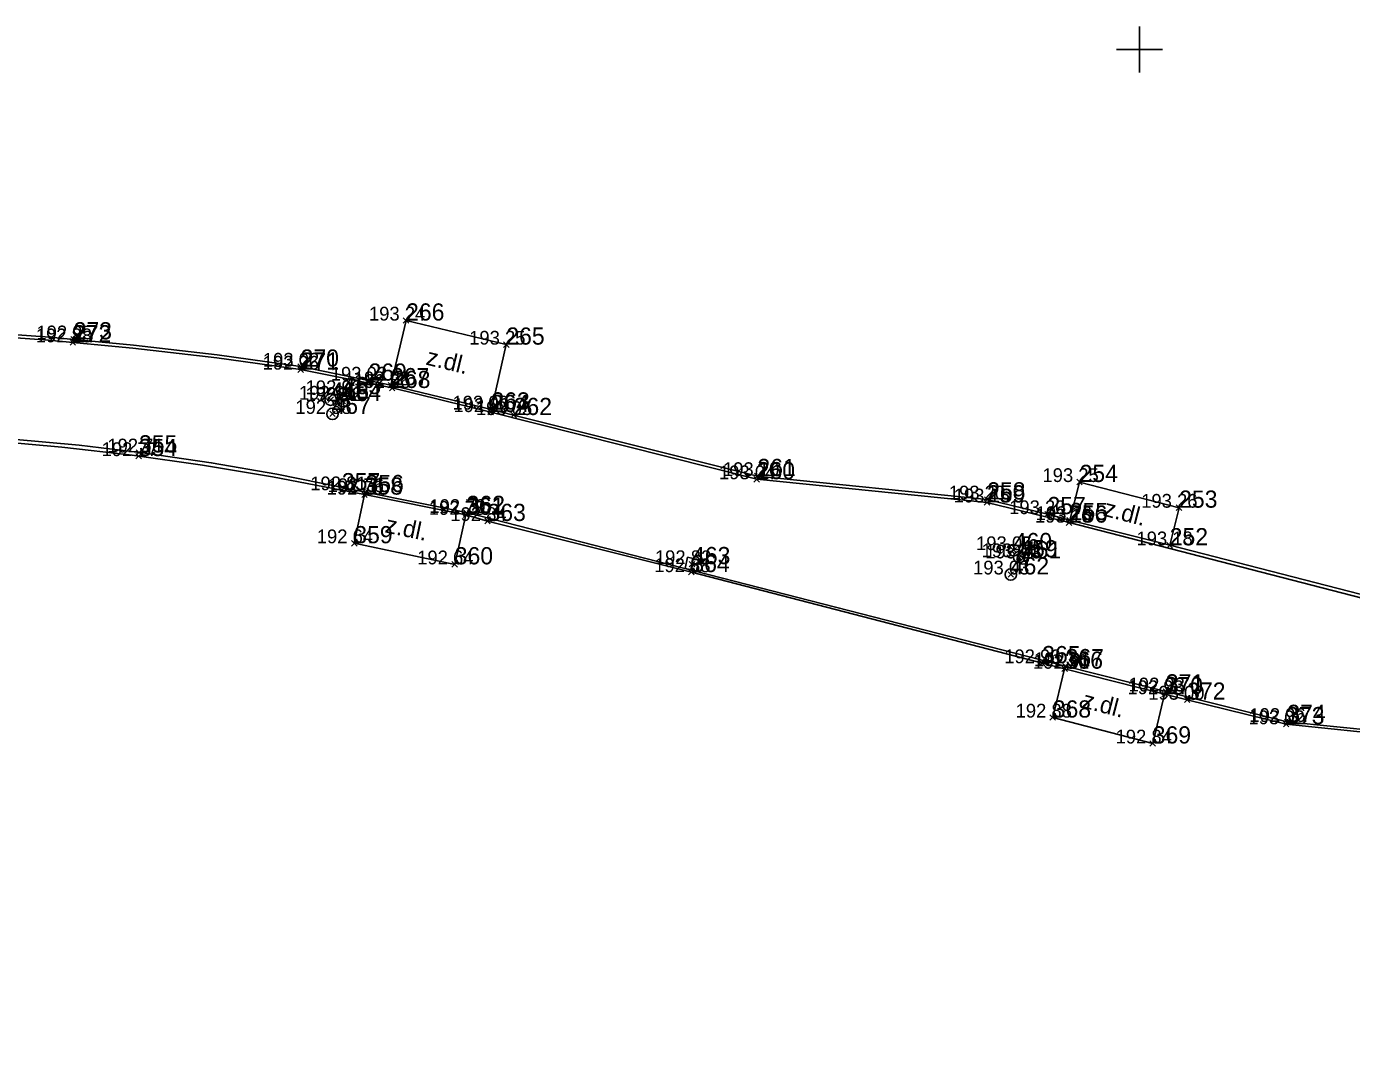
# Model space of a CAD drawing. Extents: x -706861 to -706379, y -1036456 to -1036201.
# Drawn here: x -706748.5 to -706690.8, y -1036344 to -1036299 of the extents above; entities that cross this region are included whole.
import ezdxf

# ---------------------------------------------------------------- set-up
doc = ezdxf.new("R2010")
doc.units = 0
for name, color, linetype in [('18_popisy', 7, 'Continuous'), ('29_vodovod', 7, 'Continuous'), ('30_kanalizace splašková', 7, 'Continuous'), ('40_plochy', 7, 'Continuous'), ('51_body polohopisu_značky', 7, 'Continuous'), ('52_body polohopisu_čísla', 7, 'Continuous'), ('53_body polohopisu_výšky', 7, 'Continuous'), ('54_body polohopisu_čísla nadbytečné pro kreslení', 7, 'Continuous'), ('5_rozhraní ploch', 7, 'Continuous'), ('60_mapový rám_legenda', 7, 'Continuous')]:
    doc.layers.add(name, color=color, linetype=linetype)

msp = doc.modelspace()

# ---------------------------------------------------------------- linework, layer by layer
at = {"layer": '29_vodovod'}
for centre in [(-706734.74, -1036315.03), (-706734.74, -1036315.33), (-706705.48, -1036321.83), (-706705.24, -1036322.14)]:
    msp.add_circle(centre, 0.25, dxfattribs=at)
at = {"layer": '30_kanalizace splašková'}
msp.add_line((-706719.456, -1036322.196), (-706719.564, -1036322.684), dxfattribs=at)
msp.add_lwpolyline([(-706719.701, -1036322.142), (-706719.809, -1036322.63), (-706719.32, -1036322.739), (-706719.211, -1036322.25)], close=True, dxfattribs=at)
for centre in [(-706735.27, -1036315.27), (-706735.19, -1036315.89), (-706705.08, -1036322.19), (-706705.61, -1036322.89)]:
    msp.add_circle(centre, 0.25, dxfattribs=at)
at = {"layer": '40_plochy'}
for points in [[(-706732.64, -1036314.64), (-706731.98, -1036311.82), (-706727.61, -1036312.87), (-706728.26, -1036315.7)], [(-706703.04, -1036320.52), (-706702.61, -1036318.86), (-706698.27, -1036319.98), (-706698.68, -1036321.62)], [(-706733.79, -1036319.41), (-706734.24, -1036321.53), (-706729.86, -1036322.45), (-706729.37, -1036320.29)], [(-706703.26, -1036327), (-706703.78, -1036329.13), (-706699.42, -1036330.26), (-706698.9, -1036328.11)]]:
    msp.add_lwpolyline(points, close=True, dxfattribs=at)
for points in [[(-706751.26, -1036312.41), (-706747.58, -1036312.68), (-706743.9, -1036313.03), (-706740.24, -1036313.45), (-706736.58, -1036313.96), (-706732.59, -1036314.76), (-706728.29, -1036315.81), (-706716.69, -1036318.74), (-706706.65, -1036319.75), (-706703.07, -1036320.63), (-706684.54, -1036325.41)], [(-706683.45, -1036330.34), (-706693.55, -1036329.31), (-706698.85, -1036327.99), (-706703.22, -1036326.89), (-706729.35, -1036320.19), (-706733.75, -1036319.3), (-706737.61, -1036318.52), (-706740.48, -1036318.02), (-706743.36, -1036317.6), (-706746.24, -1036317.25), (-706749.14, -1036316.99)]]:
    msp.add_lwpolyline(points, dxfattribs=at)
at = {"layer": '51_body polohopisu_značky'}
for points in [[(-706732.1, -1036311.94), (-706731.86, -1036311.7)], [(-706732.1, -1036311.7), (-706731.86, -1036311.94)], [(-706746.63, -1036312.89), (-706746.39, -1036312.65)], [(-706746.63, -1036312.65), (-706746.39, -1036312.89)], [(-706746.6, -1036312.76), (-706746.36, -1036312.52)], [(-706746.6, -1036312.52), (-706746.36, -1036312.76)], [(-706727.73, -1036312.99), (-706727.49, -1036312.75)], [(-706727.73, -1036312.75), (-706727.49, -1036312.99)], [(-706736.7, -1036313.95), (-706736.46, -1036313.71)], [(-706736.7, -1036313.71), (-706736.46, -1036313.95)], [(-706736.7, -1036314.08), (-706736.46, -1036313.84)], [(-706736.7, -1036313.84), (-706736.46, -1036314.08)], [(-706733.74, -1036314.56), (-706733.5, -1036314.32)], [(-706733.74, -1036314.32), (-706733.5, -1036314.56)], [(-706732.76, -1036314.76), (-706732.52, -1036314.52)], [(-706732.76, -1036314.52), (-706732.52, -1036314.76)], [(-706732.71, -1036314.88), (-706732.47, -1036314.64)], [(-706732.71, -1036314.64), (-706732.47, -1036314.88)], [(-706735.39, -1036315.39), (-706735.15, -1036315.15)], [(-706735.39, -1036315.15), (-706735.15, -1036315.39)], [(-706734.86, -1036315.15), (-706734.62, -1036314.91)], [(-706734.86, -1036314.91), (-706734.62, -1036315.15)], [(-706734.86, -1036315.45), (-706734.62, -1036315.21)], [(-706734.86, -1036315.21), (-706734.62, -1036315.45)], [(-706735.31, -1036316.01), (-706735.07, -1036315.77)], [(-706735.31, -1036315.77), (-706735.07, -1036316.01)], [(-706728.41, -1036315.93), (-706728.17, -1036315.69)], [(-706728.41, -1036315.69), (-706728.17, -1036315.93)], [(-706728.38, -1036315.82), (-706728.14, -1036315.58)], [(-706728.38, -1036315.58), (-706728.14, -1036315.82)], [(-706727.41, -1036316.06), (-706727.17, -1036315.82)], [(-706727.41, -1036315.82), (-706727.17, -1036316.06)], [(-706743.75, -1036317.69), (-706743.51, -1036317.45)], [(-706743.75, -1036317.45), (-706743.51, -1036317.69)], [(-706743.76, -1036317.85), (-706743.52, -1036317.61)], [(-706743.76, -1036317.61), (-706743.52, -1036317.85)], [(-706716.81, -1036318.86), (-706716.57, -1036318.62)], [(-706716.81, -1036318.62), (-706716.57, -1036318.86)], [(-706716.78, -1036318.72), (-706716.54, -1036318.48)], [(-706716.78, -1036318.48), (-706716.54, -1036318.72)], [(-706702.73, -1036318.98), (-706702.49, -1036318.74)], [(-706702.73, -1036318.74), (-706702.49, -1036318.98)], [(-706734.9, -1036319.34), (-706734.66, -1036319.1)], [(-706734.9, -1036319.1), (-706734.66, -1036319.34)], [(-706733.91, -1036319.53), (-706733.67, -1036319.29)], [(-706733.91, -1036319.29), (-706733.67, -1036319.53)], [(-706733.87, -1036319.42), (-706733.63, -1036319.18)], [(-706733.87, -1036319.18), (-706733.63, -1036319.42)], [(-706706.77, -1036319.87), (-706706.53, -1036319.63)], [(-706706.77, -1036319.63), (-706706.53, -1036319.87)], [(-706706.76, -1036319.74), (-706706.52, -1036319.5)], [(-706706.76, -1036319.5), (-706706.52, -1036319.74)], [(-706698.39, -1036320.1), (-706698.15, -1036319.86)], [(-706698.39, -1036319.86), (-706698.15, -1036320.1)], [(-706729.49, -1036320.41), (-706729.25, -1036320.17)], [(-706729.49, -1036320.17), (-706729.25, -1036320.41)], [(-706729.46, -1036320.33), (-706729.22, -1036320.09)], [(-706729.46, -1036320.09), (-706729.22, -1036320.33)], [(-706728.55, -1036320.68), (-706728.31, -1036320.44)], [(-706728.55, -1036320.44), (-706728.31, -1036320.68)], [(-706704.13, -1036320.38), (-706703.89, -1036320.14)], [(-706704.13, -1036320.14), (-706703.89, -1036320.38)], [(-706703.16, -1036320.64), (-706702.92, -1036320.4)], [(-706703.16, -1036320.4), (-706702.92, -1036320.64)], [(-706703.19, -1036320.75), (-706702.95, -1036320.51)], [(-706703.19, -1036320.51), (-706702.95, -1036320.75)], [(-706734.36, -1036321.65), (-706734.12, -1036321.41)], [(-706734.36, -1036321.41), (-706734.12, -1036321.65)], [(-706698.8, -1036321.74), (-706698.56, -1036321.5)], [(-706698.8, -1036321.5), (-706698.56, -1036321.74)], [(-706705.6, -1036321.95), (-706705.36, -1036321.71)], [(-706705.6, -1036321.71), (-706705.36, -1036321.95)], [(-706705.36, -1036322.26), (-706705.12, -1036322.02)], [(-706705.36, -1036322.02), (-706705.12, -1036322.26)], [(-706705.2, -1036322.31), (-706704.96, -1036322.07)], [(-706705.2, -1036322.07), (-706704.96, -1036322.31)], [(-706729.98, -1036322.57), (-706729.74, -1036322.33)], [(-706729.98, -1036322.33), (-706729.74, -1036322.57)], [(-706719.66, -1036322.91), (-706719.42, -1036322.67)], [(-706719.66, -1036322.67), (-706719.42, -1036322.91)], [(-706719.63, -1036322.56), (-706719.39, -1036322.32)], [(-706719.63, -1036322.32), (-706719.39, -1036322.56)], [(-706705.73, -1036323.01), (-706705.49, -1036322.77)], [(-706705.73, -1036322.77), (-706705.49, -1036323.01)], [(-706704.36, -1036326.88), (-706704.12, -1036326.64)], [(-706704.36, -1036326.64), (-706704.12, -1036326.88)], [(-706703.34, -1036327.01), (-706703.1, -1036326.77)], [(-706703.34, -1036326.77), (-706703.1, -1036327.01)], [(-706703.38, -1036327.12), (-706703.14, -1036326.88)], [(-706703.38, -1036326.88), (-706703.14, -1036327.12)], [(-706698.97, -1036328.11), (-706698.73, -1036327.87)], [(-706698.97, -1036327.87), (-706698.73, -1036328.11)], [(-706699.02, -1036328.23), (-706698.78, -1036327.99)], [(-706699.02, -1036327.99), (-706698.78, -1036328.23)], [(-706698.04, -1036328.47), (-706697.8, -1036328.23)], [(-706698.04, -1036328.23), (-706697.8, -1036328.47)], [(-706703.9, -1036329.25), (-706703.66, -1036329.01)], [(-706703.9, -1036329.01), (-706703.66, -1036329.25)], [(-706693.72, -1036329.54), (-706693.48, -1036329.3)], [(-706693.72, -1036329.3), (-706693.48, -1036329.54)], [(-706693.67, -1036329.44), (-706693.43, -1036329.2)], [(-706693.67, -1036329.2), (-706693.43, -1036329.44)], [(-706699.54, -1036330.38), (-706699.3, -1036330.14)], [(-706699.54, -1036330.14), (-706699.3, -1036330.38)]]:
    msp.add_lwpolyline(points, dxfattribs=at)
at = {"layer": '5_rozhraní ploch'}
for points in [[(-706736.58, -1036313.96), (-706740.24, -1036313.45), (-706743.9, -1036313.03), (-706747.58, -1036312.68), (-706751.26, -1036312.41), (-706754.94, -1036312.22), (-706755.47, -1036312.2), (-706758.57, -1036312.14)], [(-706736.58, -1036313.83), (-706740.22, -1036313.32), (-706743.87, -1036312.9), (-706747.52, -1036312.55), (-706751.19, -1036312.28), (-706754.86, -1036312.09), (-706755.46, -1036312.07)], [(-706728.26, -1036315.7), (-706727.61, -1036312.87), (-706731.98, -1036311.82), (-706732.64, -1036314.64)], [(-706617.25, -1036342.5), (-706639.52, -1036336.83), (-706640.49, -1036336.56), (-706644.84, -1036335.46), (-706645.81, -1036335.22), (-706668.57, -1036329.35), (-706669.52, -1036329.1), (-706673.86, -1036327.98), (-706674.82, -1036327.74), (-706684.5, -1036325.26), (-706698.68, -1036321.62), (-706703.04, -1036320.52), (-706704.01, -1036320.26), (-706706.64, -1036319.62), (-706716.66, -1036318.6), (-706727.29, -1036315.94), (-706728.26, -1036315.7), (-706732.64, -1036314.64), (-706733.62, -1036314.44), (-706736.58, -1036313.83)], [(-706611.97, -1036343.95), (-706616.32, -1036342.87), (-706620.945, -1036341.687), (-706625.407, -1036340.547), (-706640.53, -1036336.68), (-706644.87, -1036335.59), (-706669.56, -1036329.23), (-706673.91, -1036328.1), (-706684.54, -1036325.41), (-706703.07, -1036320.63), (-706706.65, -1036319.75), (-706716.69, -1036318.74), (-706728.29, -1036315.81), (-706732.59, -1036314.76), (-706736.58, -1036313.96)], [(-706734.78, -1036319.22), (-706737.81, -1036318.63), (-706740.86, -1036318.12), (-706743.92, -1036317.69), (-706746.99, -1036317.34), (-706750.07, -1036317.07), (-706753.15, -1036316.88), (-706753.61, -1036316.86)], [(-706734.76, -1036319.1), (-706737.61, -1036318.52), (-706740.48, -1036318.02), (-706743.36, -1036317.6), (-706746.24, -1036317.25), (-706749.14, -1036316.99), (-706752.05, -1036316.81), (-706753.6, -1036316.74)], [(-706734.78, -1036319.22), (-706733.79, -1036319.41), (-706729.37, -1036320.29), (-706728.43, -1036320.56), (-706719.54, -1036322.79), (-706704.23, -1036326.76), (-706703.26, -1036327), (-706698.9, -1036328.11), (-706697.92, -1036328.35), (-706693.6, -1036329.42), (-706683.51, -1036330.46), (-706676.23, -1036332.35), (-706675.29, -1036332.57), (-706670.89, -1036333.7)], [(-706734.76, -1036319.1), (-706733.75, -1036319.3), (-706729.35, -1036320.19)], [(-706698.68, -1036321.62), (-706698.27, -1036319.98), (-706702.61, -1036318.86), (-706703.04, -1036320.52)], [(-706733.79, -1036319.41), (-706734.24, -1036321.53), (-706729.86, -1036322.45), (-706729.37, -1036320.29)], [(-706729.35, -1036320.19), (-706703.22, -1036326.89), (-706698.85, -1036327.99), (-706693.55, -1036329.31), (-706683.45, -1036330.34), (-706675.27, -1036332.47)], [(-706703.26, -1036327), (-706703.78, -1036329.13), (-706699.42, -1036330.26), (-706698.9, -1036328.11)]]:
    msp.add_lwpolyline(points, dxfattribs=at)
at = {"layer": '60_mapový rám_legenda'}
for points in [[(-706700, -1036299), (-706700, -1036300), (-706700, -1036301)], [(-706699, -1036300), (-706700, -1036300), (-706701, -1036300)]]:
    msp.add_lwpolyline(points, dxfattribs=at)

# ---------------------------------------------------------------- texts
at = {"layer": '18_popisy'}
for rotation, p in [(346.39547, (-706731.154, -1036313.735)), (345.52971, (-706701.606, -1036320.325)), (348.13772, (-706732.934, -1036321.051)), (345.47011, (-706702.542, -1036328.682))]:
    msp.add_text('z.dl.', height=0.75, rotation=rotation, dxfattribs=at).set_placement(p)
at = {"layer": '52_body polohopisu_čísla'}
for s, p in [('266', (-706731.98, -1036311.82)), ('272', (-706746.51, -1036312.77)), ('271', (-706736.58, -1036313.96)), ('263', (-706728.26, -1036315.7)), ('354', (-706743.64, -1036317.73)), ('261', (-706716.66, -1036318.6)), ('254', (-706702.61, -1036318.86)), ('356', (-706733.75, -1036319.3)), ('258', (-706706.64, -1036319.62)), ('253', (-706698.27, -1036319.98)), ('363', (-706728.43, -1036320.56)), ('257', (-706704.01, -1036320.26)), ('252', (-706698.68, -1036321.62)), ('360', (-706729.86, -1036322.45)), ('364', (-706719.54, -1036322.79)), ('462', (-706705.61, -1036322.89)), ('365', (-706704.24, -1036326.76)), ('372', (-706697.92, -1036328.35)), ('373', (-706693.6, -1036329.42)), ('369', (-706699.42, -1036330.26))]:
    msp.add_text(s, height=0.75, dxfattribs=at).set_placement(p)
at = {"layer": '53_body polohopisu_výšky'}
for s, p in [('193 24 ', (-706733.598, -1036311.82)), ('192 88 ', (-706748.128, -1036312.77)), ('192 95 ', (-706748.1, -1036312.64)), ('193 25 ', (-706729.228, -1036312.87)), ('192 96 ', (-706738.233, -1036313.96)), ('193 02 ', (-706738.224, -1036313.83)), ('193 02 ', (-706735.264, -1036314.44)), ('192 98 ', (-706734.26, -1036314.64)), ('192 91 ', (-706736.649, -1036315.27)), ('192 93 ', (-706736.36, -1036315.03)), ('192 96 ', (-706734.243, -1036314.76)), ('192 92 ', (-706736.36, -1036315.33)), ('193 00 ', (-706729.956, -1036315.7)), ('192 99 ', (-706729.915, -1036315.81)), ('192 88 ', (-706736.808, -1036315.89)), ('193 05 ', (-706728.934, -1036315.94)), ('192 71 ', (-706745.007, -1036317.57)), ('192 77 ', (-706745.258, -1036317.73)), ('193 04 ', (-706718.334, -1036318.74)), ('193 10 ', (-706718.16, -1036318.6)), ('192 81 ', (-706736.157, -1036319.22)), ('192 76 ', (-706735.401, -1036319.3)), ('193 25 ', (-706704.228, -1036318.86)), ('192 76 ', (-706735.441, -1036319.41)), ('193 20 ', (-706708.31, -1036319.62)), ('193 15 ', (-706708.098, -1036319.75)), ('192 78 ', (-706730.988, -1036320.29)), ('192 79 ', (-706730.963, -1036320.21)), ('193 20 ', (-706705.68, -1036320.26)), ('193 26 ', (-706699.921, -1036319.98)), ('192 84 ', (-706730.048, -1036320.56)), ('193 16 ', (-706704.551, -1036320.63)), ('193 16 ', (-706704.521, -1036320.52)), ('192 64 ', (-706735.875, -1036321.53)), ('193 18 ', (-706700.128, -1036321.62)), ('193 05 ', (-706707.124, -1036321.83)), ('193 04 ', (-706706.884, -1036322.14)), ('193 03 ', (-706706.724, -1036322.19)), ('192 64 ', (-706731.495, -1036322.45)), ('192 88 ', (-706721.158, -1036322.79)), ('192 82 ', (-706721.128, -1036322.44)), ('193 03 ', (-706707.254, -1036322.89)), ('192 96 ', (-706705.893, -1036326.76)), ('192 91 ', (-706704.639, -1036327)), ('192 91 ', (-706704.599, -1036326.89)), ('192 93 ', (-706700.47, -1036327.99)), ('192 93 ', (-706700.52, -1036328.11)), ('193 00 ', (-706699.616, -1036328.35)), ('192 88 ', (-706705.398, -1036329.13)), ('193 02 ', (-706695.244, -1036329.42)), ('192 96 ', (-706695.203, -1036329.32)), ('192 84 ', (-706701.038, -1036330.26))]:
    msp.add_text(s, height=0.6, dxfattribs=at).set_placement(p)
at = {"layer": '54_body polohopisu_čísla nadbytečné pro kreslení'}
for s, p in [('273', (-706746.48, -1036312.64)), ('265', (-706727.61, -1036312.87)), ('270', (-706736.58, -1036313.83)), ('269', (-706733.62, -1036314.44)), ('267', (-706732.64, -1036314.64)), ('268', (-706732.59, -1036314.76)), ('466', (-706735.27, -1036315.27)), ('465', (-706734.74, -1036315.03)), ('464', (-706734.74, -1036315.33)), ('467', (-706735.19, -1036315.89)), ('264', (-706728.29, -1036315.81)), ('262', (-706727.29, -1036315.94)), ('355', (-706743.63, -1036317.57)), ('260', (-706716.69, -1036318.74)), ('357', (-706734.78, -1036319.22)), ('358', (-706733.79, -1036319.41)), ('259', (-706706.65, -1036319.75)), ('361', (-706729.37, -1036320.29)), ('362', (-706729.34, -1036320.21)), ('256', (-706703.07, -1036320.63)), ('255', (-706703.04, -1036320.52)), ('359', (-706734.24, -1036321.53)), ('460', (-706705.48, -1036321.83)), ('459', (-706705.24, -1036322.14)), ('461', (-706705.08, -1036322.19)), ('463', (-706719.51, -1036322.44)), ('366', (-706703.26, -1036327)), ('367', (-706703.22, -1036326.89)), ('370', (-706698.9, -1036328.11)), ('371', (-706698.85, -1036327.99)), ('368', (-706703.78, -1036329.13)), ('374', (-706693.55, -1036329.32))]:
    msp.add_text(s, height=0.75, dxfattribs=at).set_placement(p)

doc.saveas('drawing.dxf')
